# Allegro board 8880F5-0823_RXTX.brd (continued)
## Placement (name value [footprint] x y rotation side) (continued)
NOREF#2160  -  []  384.08 209.16 90 top
NOREF#2161  -  []  252.51 265.56 90 top
NOREF#2162  -  []  351.04 189.82 0 top
NOREF#2163  -  []  259.88 288.41 90 top
NOREF#2164  -  []  192.47 232.37 90 top
NOREF#2165  -  []  310.73 249.2 0 top
NOREF#2166  -  []  390.53 154.88 0 top
NOREF#2167  -  []  379.48 222.7 90 top
NOREF#2168  -  []  511.59 273.87 90 top
NOREF#2169  -  []  412.62 273.37 0 top
NOREF#2170  -  []  94.93 190.55 0 top
NOREF#2171  -  []  263.95 163.52 90 top
NOREF#2172  -  []  383.09 289.12 0 top
NOREF#2173  -  []  229.51 193.69 0 top
NOREF#2174  -  []  303.84 288.86 0 top
NOREF#2175  -  []  167.7 229.07 90 top
NOREF#2176  -  []  453.88 171.53 0 top
NOREF#2177  -  []  327.27 131.64 90 top
NOREF#2178  -  []  182.57 158.5 0 top
NOREF#2179  -  []  252.51 205.55 0 top
NOREF#2180  -  []  383.09 224.85 0 top
NOREF#2181  -  []  209.23 216.45 90 top
NOREF#2182  -  []  400.85 265.37 0 top
NOREF#2183  -  []  330.17 163.82 90 top
NOREF#2184  -  []  383.09 241.11 0 top
NOREF#2185  -  []  518.38 290.38 90 top
NOREF#2186  -  []  182.82 230.19 90 top
NOREF#2187  -  []  272.25 244.23 0 top
NOREF#2188  -  []  406.19 171.64 0 top
NOREF#2189  -  []  167.7 260.9 90 top
NOREF#2190  -  []  413.51 207.71 90 top
NOREF#2191  -  []  175.7 162.1 90 top
NOREF#2192  -  []  209.23 202.99 90 top
NOREF#2193  -  []  331.86 252.43 90 top
NOREF#2194  -  []  471.21 168.33 90 top
NOREF#2195  -  []  250.74 164.72 0 top
NOREF#2196  -  []  256.45 164.74 0 top
NOREF#2197  -  []  390.94 257.16 90 top
NOREF#2198  -  []  167.7 247.18 90 top
NOREF#2199  -  []  215.96 248.49 0 top
NOREF#2200  -  []  184.89 159.1 90 top
NOREF#2201  -  []  377.32 180.15 0 top
NOREF#2202  -  []  423.61 182.42 90 top
NOREF#2203  -  []  330.17 225.04 90 top
NOREF#2204  -  []  230.41 243.09 90 top
NOREF#2205  -  []  309.51 249.2 0 top
NOREF#2206  -  []  329.85 164.72 0 top
NOREF#2207  -  []  184.89 172.56 90 top
NOREF#2208  -  []  450.03 166.93 0 top
NOREF#2209  -  []  194.09 187.32 90 top
NOREF#2210  -  []  381.86 129.99 0 top
NOREF#2211  -  []  201.23 192.32 90 top
NOREF#2212  -  []  327.25 265.55 0 top
NOREF#2213  -  []  192.57 256.4 90 top
NOREF#2214  -  []  392.24 193.43 90 top
NOREF#2215  -  []  182.57 158.5 90 top
NOREF#2216  -  []  167.7 134.07 90 top
NOREF#2217  -  []  388.43 180.15 0 top
NOREF#2218  -  []  184.47 200.54 90 top
NOREF#2219  -  []  199.33 226.57 0 top
NOREF#2220  -  []  230.73 249.2 0 top
NOREF#2221  -  []  248.33 187.93 0 top
NOREF#2222  -  []  229.51 249.2 0 top
NOREF#2223  -  []  478.57 274.77 90 top
NOREF#2224  -  []  247.57 264.65 90 top
NOREF#2225  -  []  201.23 200.54 0 top
NOREF#2226  -  []  334.29 265.56 0 top
NOREF#2227  -  []  420.62 239.21 90 top
NOREF#2228  -  []  192.47 222.95 90 top
NOREF#2229  -  []  167.7 206.29 90 top
NOREF#2230  -  []  237.83 257.63 0 top
NOREF#2231  -  []  298.16 188.49 0 top
NOREF#2232  -  []  194.09 255.9 90 top
NOREF#2233  -  []  124.61 178.64 0 top
NOREF#2234  -  []  336.45 224.74 0 top
NOREF#2235  -  []  399.39 178.25 0 top
NOREF#2236  -  []  172.08 275.14 90 top
NOREF#2237  -  []  101.82 290.38 90 top
NOREF#2238  -  []  321.82 227.13 90 top
NOREF#2239  -  []  262.68 224.74 90 top
NOREF#2240  -  []  260.99 135.19 90 top
NOREF#2241  -  []  230.73 189.2 0 top
NOREF#2242  -  []  201.23 233.47 90 top
NOREF#2243  -  []  420.62 271.47 90 top
NOREF#2244  -  []  238.45 257.01 0 top
NOREF#2245  -  []  410.27 257.37 0 top
NOREF#2246  -  []  263.95 224.74 90 top
NOREF#2247  -  []  184.47 186.57 90 top
NOREF#2248  -  []  394.46 129.99 90 top
NOREF#2249  -  []  229.21 253.37 0 top
NOREF#2250  -  []  119.95 195.15 0 top
NOREF#2251  -  []  451.68 214.96 0 top
NOREF#2252  -  []  387.08 154.88 0 top
NOREF#2253  -  []  367.13 271.21 0 top
NOREF#2254  -  []  309.51 193.69 0 top
NOREF#2255  -  []  400.91 207.71 0 top
NOREF#2256  -  []  251.05 264.65 90 top
NOREF#2257  -  []  209.23 230.17 90 top
NOREF#2258  -  []  330.73 205.55 0 top
NOREF#2259  -  []  387.39 265.11 0 top
NOREF#2260  -  []  232.25 271.67 90 top
NOREF#2261  -  []  251.62 265.56 0 top
NOREF#2262  -  []  331.05 265.86 90 top
NOREF#2263  -  []  217.41 213.24 90 top
NOREF#2264  -  []  318.45 257.01 0 top
NOREF#2265  -  []  473.7 176.22 90 top
NOREF#2266  -  []  451.64 179.06 0 top
NOREF#2267  -  []  318.32 131.64 0 top
NOREF#2268  -  []  277.17 288.86 0 top
NOREF#2269  -  []  165.8 185.42 0 top
NOREF#2270  -  []  378.75 240.56 90 top
NOREF#2271  -  []  199.33 212.85 0 top
NOREF#2272  -  []  230.73 187.93 0 top
NOREF#2273  -  []  175.7 230.17 90 top
NOREF#2274  -  []  251.54 192.73 90 top
NOREF#2275  -  []  384.36 131.89 0 top
NOREF#2276  -  []  167.7 241.43 0 top
NOREF#2277  -  []  184.47 173.11 90 top
NOREF#2278  -  []  392.47 240.66 90 top
NOREF#2279  -  []  403.99 171.64 0 top
NOREF#2280  -  []  400.25 148.15 90 top
NOREF#2281  -  []  318.32 131.64 0 top
NOREF#2282  -  []  317.05 288.86 0 top
NOREF#2283  -  []  268.94 272.1 0 top
NOREF#2284  -  []  272.25 241.69 0 top
NOREF#2285  -  []  310.73 183.41 0 top
NOREF#2286  -  []  167.7 186.57 0 top
NOREF#2287  -  []  346.27 135.17 90 top
NOREF#2288  -  []  385.19 297.12 0 top
NOREF#2289  -  []  376.98 224.6 0 top
NOREF#2290  -  []  247.25 204.35 90 top
NOREF#2291  -  []  254.61 264.65 90 top
NOREF#2292  -  []  337.09 223.52 90 top
NOREF#2293  -  []  303.56 173.86 90 top
NOREF#2294  -  []  451.68 171.53 0 top
NOREF#2295  -  []  300.11 273.24 90 top
NOREF#2296  -  []  415.1 163.64 0 top
NOREF#2297  -  []  110.47 171.02 0 top
NOREF#2298  -  []  300.36 248.49 0 top
NOREF#2299  -  []  451.68 195.91 0 top
NOREF#2300  -  []  475.04 195.66 0 top
NOREF#2301  -  []  352.25 189.18 90 top
NOREF#2302  -  []  337.9 186.99 0 top
NOREF#2303  -  []  459.28 227 0 top
NOREF#2304  -  []  185.2 273.5 90 top
NOREF#2305  -  []  117.33 247.35 90 top
NOREF#2306  -  []  401.87 194.18 90 top
NOREF#2307  -  []  182.57 226.57 90 top
NOREF#2308  -  []  217.41 273.24 90 top
NOREF#2309  -  []  253.4 265.55 0 top
NOREF#2310  -  []  379 272.56 90 top
NOREF#2311  -  []  209.49 182.06 90 top
NOREF#2312  -  []  390.94 224.9 90 top
NOREF#2313  -  []  381.74 232.85 0 top
NOREF#2314  -  []  115.87 175.44 90 top
NOREF#2315  -  []  184.47 163.2 90 top
NOREF#2316  -  []  379.73 287.22 90 top
NOREF#2317  -  []  368.03 265.11 0 top
NOREF#2318  -  []  167.7 219.75 90 top
NOREF#2319  -  []  192.47 264.1 90 top
NOREF#2320  -  []  352.24 189.18 90 top
NOREF#2321  -  []  310.43 193.37 90 top
NOREF#2322  -  []  310.41 248.88 90 top
NOREF#2323  -  []  317.05 288.86 0 top
NOREF#2324  -  []  215.96 248.49 0 top
NOREF#2325  -  []  296.96 240.71 0 top
NOREF#2326  -  []  310.73 253.69 0 top
NOREF#2327  -  []  465.45 273.87 90 top
NOREF#2328  -  []  260.99 143.19 0 top
NOREF#2329  -  []  298.16 177.06 0 top
NOREF#2330  -  []  93.76 273.87 90 top
NOREF#2331  -  []  461.86 230.75 0 top
NOREF#2332  -  []  272.25 184.23 0 top
NOREF#2333  -  []  450.03 182.17 0 top
NOREF#2334  -  []  315.7 296.86 0 top
NOREF#2335  -  []  331.62 265.56 0 top
NOREF#2336  -  []  302.49 296.86 0 top
NOREF#2337  -  []  327.89 204.35 90 top
NOREF#2338  -  []  118.45 226.62 90 top
NOREF#2339  -  []  511.59 293.82 90 top
NOREF#2340  -  []  403.41 209.61 0 top
NOREF#2341  -  []  271.04 244.23 0 top
NOREF#2342  -  []  192.47 209.49 90 top
NOREF#2343  -  []  107.02 171.57 0 top
NOREF#2344  -  []  324.65 288.86 0 top
NOREF#2345  -  []  165.8 171.96 90 top
NOREF#2346  -  []  287.27 286.96 90 top
NOREF#2347  -  []  313.98 143.79 90 top
NOREF#2348  -  []  352.55 189.5 0 top
NOREF#2349  -  []  184.47 227.72 0 top
NOREF#2350  -  []  395.07 129.99 0 top
NOREF#2351  -  []  295.96 248.49 0 top
NOREF#2352  -  []  411.26 163.09 90 top
NOREF#2353  -  []  332.51 205.56 0 top
NOREF#2354  -  []  473.6 162.62 90 top
NOREF#2355  -  []  379.48 255.21 90 top
NOREF#2356  -  []  184.47 173.11 0 top
NOREF#2357  -  []  175.7 135.17 90 top
NOREF#2358  -  []  333.33 181.33 90 top
NOREF#2359  -  []  392.24 193.43 0 top
NOREF#2360  -  []  251.94 264.65 90 top
NOREF#2361  -  []  271.04 181.69 0 top
NOREF#2362  -  []  127.84 167.9 90 top
NOREF#2363  -  []  392.04 273.11 90 top
NOREF#2364  -  []  251.86 192.43 90 top
NOREF#2365  -  []  234.7 298.51 0 top
NOREF#2366  -  []  375.22 163.39 0 top
NOREF#2367  -  []  229.51 183.41 0 top
NOREF#2368  -  []  387.39 249.11 0 top
NOREF#2369  -  []  304.61 144.34 0 top
NOREF#2370  -  []  199.33 199.39 90 top
NOREF#2371  -  []  398.65 209.36 90 top
NOREF#2372  -  []  101.82 273.87 90 top
NOREF#2373  -  []  396.55 257.37 0 top
NOREF#2374  -  []  199.08 254 0 top
NOREF#2375  -  []  401.89 163.64 0 top
NOREF#2376  -  []  391.96 131.89 0 top
NOREF#2377  -  []  271.04 241.69 0 top
NOREF#2378  -  []  298.13 214.06 0 top
NOREF#2379  -  []  310.43 248.88 0 top
NOREF#2380  -  []  343.98 288.86 0 top
NOREF#2381  -  []  410.52 273.37 0 top
NOREF#2382  -  []  124.39 214.79 0 top
NOREF#2383  -  []  384.36 131.89 0 top
NOREF#2384  -  []  272.25 182.96 0 top
NOREF#2385  -  []  226.27 216.63 90 top
NOREF#2386  -  []  175.7 218.65 90 top
NOREF#2387  -  []  343.2 232.26 90 top
NOREF#2388  -  []  306.27 156.63 90 top
NOREF#2389  -  []  460.93 234.74 90 top
NOREF#2390  -  []  289.01 272.1 0 top
NOREF#2391  -  []  461.86 187.32 0 top
NOREF#2392  -  []  120.21 178.64 0 top
NOREF#2393  -  []  230.73 183.41 0 top
NOREF#2394  -  []  396.55 289.12 0 top
NOREF#2395  -  []  331.62 264.35 90 top
NOREF#2396  -  []  201.49 161 90 top
NOREF#2397  -  []  479.44 195.66 0 top
NOREF#2398  -  []  184.47 206.29 90 top
NOREF#2399  -  []  390.69 289.12 0 top
NOREF#2400  -  []  339.65 204.65 90 top
NOREF#2401  -  []  112.41 195.15 0 top
NOREF#2402  -  []  244.8 288.61 0 top
NOREF#2403  -  []  257.9 246.35 90 top
NOREF#2404  -  []  262.34 143.19 0 top
NOREF#2405  -  []  297.41 213.24 90 top
NOREF#2406  -  []  312.46 144.39 90 top
NOREF#2407  -  []  418.12 241.11 0 top
NOREF#2408  -  []  304.61 144.34 0 top
NOREF#2409  -  []  317.57 209.63 90 top
NOREF#2410  -  []  264.29 272.1 90 top
NOREF#2411  -  []  346.27 135.17 90 top
NOREF#2412  -  []  468.85 259.9 90 top
NOREF#2413  -  []  310.43 243.09 90 top
NOREF#2414  -  []  395.2 249.11 0 top
NOREF#2415  -  []  230.43 248.88 90 top
NOREF#2416  -  []  368.03 232.6 0 top
NOREF#2417  -  []  229.05 211.67 0 top
NOREF#2418  -  []  392.47 288.57 90 top
NOREF#2419  -  []  194.09 242.18 90 top
NOREF#2420  -  []  342.68 164.74 90 top
NOREF#2421  -  []  390.53 163.64 0 top
NOREF#2422  -  []  485.36 292.02 90 top
NOREF#2423  -  []  168.13 145.38 90 top
NOREF#2424  -  []  320.42 139.64 0 top
NOREF#2425  -  []  184.89 240.88 90 top
NOREF#2426  -  []  201.21 292.55 90 top
NOREF#2427  -  []  385.32 161.49 90 top
NOREF#2428  -  []  184.89 227.17 90 top
NOREF#2429  -  []  459.28 183.57 90 top
NOREF#2430  -  []  182.82 162.12 90 top
NOREF#2431  -  []  250.49 164.74 90 top
NOREF#2432  -  []  93.76 271.33 90 top
NOREF#2433  -  []  199.84 148.65 90 top
NOREF#2434  -  []  272.24 241.05 90 top
NOREF#2435  -  []  339.33 264.35 90 top
NOREF#2436  -  []  166.06 243.9 90 top
NOREF#2437  -  []  462.06 277.31 90 top
NOREF#2438  -  []  175.7 243.88 90 top
NOREF#2439  -  []  272.25 242.32 90 top
NOREF#2440  -  []  239.33 176.03 90 top
NOREF#2441  -  []  394.66 290.39 90 top
NOREF#2442  -  []  470.79 128.27 0 top
NOREF#2443  -  []  286.55 288.31 90 top
NOREF#2444  -  []  327.89 264.35 90 top
NOREF#2445  -  []  251.62 265.55 0 top
NOREF#2446  -  []  175.7 195.52 90 top
NOREF#2447  -  []  209.49 162.1 90 top
NOREF#2448  -  []  166.06 257.62 90 top
NOREF#2449  -  []  334.61 204.65 90 top
NOREF#2450  -  []  396.55 225.11 0 top
NOREF#2451  -  []  106.76 210.11 90 top
NOREF#2452  -  []  201.49 147.53 90 top
NOREF#2453  -  []  165.8 240.28 0 top
NOREF#2454  -  []  369.38 224.6 0 top
NOREF#2455  -  []  419.9 240.56 90 top
NOREF#2456  -  []  184.89 186.02 90 top
NOREF#2457  -  []  118.96 179.19 0 top
NOREF#2458  -  []  101.82 271.33 90 top
NOREF#2459  -  []  413.75 171.64 0 top
NOREF#2460  -  []  331.62 205.56 90 top
NOREF#2461  -  []  463.61 171.53 0 top
NOREF#2462  -  []  184.47 219.75 90 top
NOREF#2463  -  []  251.06 165.04 90 top
NOREF#2464  -  []  115.36 235.64 90 top
NOREF#2465  -  []  405.93 272.66 90 top
NOREF#2466  -  []  377.23 289.12 0 top
NOREF#2467  -  []  479.44 239.09 0 top
NOREF#2468  -  []  528.1 276.41 90 top
NOREF#2469  -  []  175.7 189.02 90 top
NOREF#2470  -  []  459.28 168.33 90 top
NOREF#2471  -  []  327.25 205.55 0 top
NOREF#2472  -  []  272.55 185.18 0 top
NOREF#2473  -  []  346.08 296.86 0 top
NOREF#2474  -  []  165.8 171.96 0 top
NOREF#2475  -  []  36.1 131.91 0 top
NOREF#2476  -  []  127.95 187.53 0 top
NOREF#2477  -  []  249.6 164.74 90 top
NOREF#2478  -  []  384.59 162.84 90 top
NOREF#2479  -  []  411.26 209.66 90 top
NOREF#2480  -  []  451.68 230.2 0 top
NOREF#2481  -  []  250.73 205.56 0 top
NOREF#2482  -  []  352.25 249.82 0 top
NOREF#2483  -  []  451.68 171.53 0 top
NOREF#2484  -  []  462.06 274.77 90 top
NOREF#2485  -  []  386.33 207.21 90 top
NOREF#2486  -  []  393.19 287.22 90 top
NOREF#2487  -  []  128.21 178.64 0 top
NOREF#2488  -  []  400.24 198.08 90 top
NOREF#2489  -  []  200.98 260.9 90 top
NOREF#2490  -  []  108.01 222.33 0 top
NOREF#2491  -  []  263.2 172.26 90 top
NOREF#2492  -  []  249.28 223.82 90 top
NOREF#2493  -  []  35.83 132.61 0 top
NOREF#2494  -  []  337.09 163.52 90 top
NOREF#2495  -  []  263.31 224.74 0 top
NOREF#2496  -  []  461.96 210.36 0 top
NOREF#2497  -  []  192.47 164.3 90 top
NOREF#2498  -  []  418.12 257.42 90 top
NOREF#2499  -  []  115.61 211.51 90 top
NOREF#2500  -  []  461.86 225.6 90 top
NOREF#2501  -  []  352.93 288.86 90 top
NOREF#2502  -  []  394.05 255.47 0 top
NOREF#2503  -  []  463.61 222.58 0 top
NOREF#2504  -  []  259.97 264.35 90 top
NOREF#2505  -  []  392.47 272.56 90 top
NOREF#2506  -  []  398.53 178.25 90 top
NOREF#2507  -  []  471.21 211.76 0 top
NOREF#2508  -  []  485.36 259.9 90 top
NOREF#2509  -  []  303.56 185.29 90 top
NOREF#2510  -  []  334.61 205.86 90 top
NOREF#2511  -  []  386.53 181.42 90 top
NOREF#2512  -  []  368.28 281.11 0 top
NOREF#2513  -  []  254.29 205.55 0 top
NOREF#2514  -  []  194.09 160.4 90 top
NOREF#2515  -  []  383.09 273.11 0 top
NOREF#2516  -  []  465.31 186.77 0 top
NOREF#2517  -  []  449.99 174.46 0 top
NOREF#2518  -  []  253.53 140.14 0 top
NOREF#2519  -  []  229.21 243.09 0 top
NOREF#2520  -  []  201.49 178.86 90 top
NOREF#2521  -  []  199.33 185.42 90 top
NOREF#2522  -  []  230.73 189.2 0 top
NOREF#2523  -  []  392.04 257.11 90 top
NOREF#2524  -  []  461.96 166.93 0 top
NOREF#2525  -  []  330.74 224.74 0 top
NOREF#2526  -  []  383.09 224.85 0 top
NOREF#2527  -  []  249.85 224.74 0 top
NOREF#2528  -  []  259.33 205.55 0 top
NOREF#2529  -  []  310.73 189.2 0 top
NOREF#2530  -  []  352.24 242.32 90 top
NOREF#2531  -  []  242.23 173.13 0 top
NOREF#2532  -  []  309.51 187.93 0 top
NOREF#2533  -  []  242.23 233.13 0 top
NOREF#2534  -  []  329.28 165.04 90 top
NOREF#2535  -  []  182.57 144.78 90 top
NOREF#2536  -  []  471.21 219.38 0 top
NOREF#2537  -  []  105.93 204.27 90 top
NOREF#2538  -  []  420.15 131.44 90 top
NOREF#2539  -  []  184.47 151.68 90 top
NOREF#2540  -  []  230.43 194.01 0 top
NOREF#2541  -  []  354.27 134.07 90 top
NOREF#2542  -  []  210.86 242.18 90 top
NOREF#2543  -  []  310.43 188.88 90 top
NOREF#2544  -  []  75.98 287.84 90 top
NOREF#2545  -  []  184.47 214 0 top
NOREF#2546  -  []  314.33 228.13 90 top
NOREF#2547  -  []  329.6 223.52 90 top
NOREF#2548  -  []  109.96 238.84 0 top
NOREF#2549  -  []  271.04 245.5 0 top
NOREF#2550  -  []  118.74 215.34 0 top
NOREF#2551  -  []  310.41 247.61 90 top
NOREF#2552  -  []  296.96 192.14 0 top
NOREF#2553  -  []  334.29 205.56 0 top
NOREF#2554  -  []  354.27 131.87 90 top
NOREF#2555  -  []  167.7 214 0 top
NOREF#2556  -  []  298.16 237.06 0 top
NOREF#2557  -  []  397.8 146.33 90 top
NOREF#2558  -  []  248 286.96 0 top
NOREF#2559  -  []  318.45 197.01 0 top
NOREF#2560  -  []  230.41 247.61 90 top
NOREF#2561  -  []  263.71 288.86 0 top
NOREF#2562  -  []  409.17 249.11 0 top
NOREF#2563  -  []  405.93 272.56 90 top
NOREF#2564  -  []  396.28 146.93 90 top
NOREF#2565  -  []  201.23 227.72 0 top
NOREF#2566  -  []  229.51 186.66 0 top
NOREF#2567  -  []  118.99 171.65 0 top
NOREF#2568  -  []  424.55 146.88 90 top
NOREF#2569  -  []  301.34 286.96 0 top
NOREF#2570  -  []  339.65 264.65 90 top
NOREF#2571  -  []  453.84 179.06 0 top
NOREF#2572  -  []  401.89 163.64 0 top
R1  NC/1M-1-S4  [R0402]  221.23 227.84 180 bottom
R2  NC/1M-1-S4  [R0402]  218.95 227.84 0 bottom
R3  NC/100K-1-S4  [R0402]  184.15 131.06 180 bottom
R4  NC/100K-1-S4  [R0402]  181.61 131.06 180 bottom
R5  0-5-S4  [R0402]  222.38 272.16 270 bottom
R6  1M-1-S4  [R0402]  222.38 274.32 270 bottom
R7  49.9-1-S4  [R0402]  178.5 217.52 90 bottom
R8  49.9-1-S4  [R0402]  178.5 215.38 90 bottom
R9  49.9-1-S4  [R0402]  164.91 217.52 90 bottom
R10  49.9-1-S4  [R0402]  164.91 215.38 90 bottom
R11  49.9-1-S4  [R0402]  212.03 231.24 90 bottom
R12  49.9-1-S4  [R0402]  212.03 229.1 90 bottom
R13  49.9-1-S4  [R0402]  198.44 231.24 90 bottom
R14  49.9-1-S4  [R0402]  198.44 229.1 90 bottom
R15  49.9-1-S4  [R0402]  296.06 299.66 180 bottom
R16  49.9-1-S4  [R0402]  298.21 299.66 180 bottom
R17  49.9-1-S4  [R0402]  296.06 286.07 180 bottom
R18  49.9-1-S4  [R0402]  298.21 286.07 180 bottom
R19  49.9-1-S4  [R0402]  309.27 299.66 180 bottom
R20  49.9-1-S4  [R0402]  311.42 299.66 180 bottom
R21  49.9-1-S4  [R0402]  309.27 286.07 180 bottom
R22  49.9-1-S4  [R0402]  311.42 286.07 180 bottom
R23  49.9-1-S4  [R0402]  349.4 299.66 180 bottom
R24  49.9-1-S4  [R0402]  351.55 299.66 180 bottom
R25  49.9-1-S4  [R0402]  349.4 286.07 180 bottom
R26  49.9-1-S4  [R0402]  351.55 286.07 180 bottom
R27  49.9-1-S4  [R0402]  335.94 299.66 180 bottom
R28  49.9-1-S4  [R0402]  338.09 299.66 180 bottom
R29  49.9-1-S4  [R0402]  335.94 286.07 180 bottom
R30  49.9-1-S4  [R0402]  338.09 286.07 180 bottom
R31  49.9-1-S4  [R0402]  322.48 299.66 180 bottom
R32  49.9-1-S4  [R0402]  324.62 299.66 180 bottom
R33  49.9-1-S4  [R0402]  322.48 286.07 180 bottom
R34  49.9-1-S4  [R0402]  324.62 286.07 180 bottom
R37  49.9-1-S4  [R0402]  269.14 286.07 180 bottom
R38  49.9-1-S4  [R0402]  271.28 286.07 180 bottom
R39  49.9-1-S4  [R0402]  287.88 269.3 0 bottom
R40  49.9-1-S4  [R0402]  285.74 269.3 0 bottom
R41  49.9-1-S4  [R0402]  287.88 282.89 0 bottom
R42  49.9-1-S4  [R0402]  285.74 282.89 0 bottom
R43  49.9-1-S4  [R0402]  164.91 258.67 90 bottom
R44  49.9-1-S4  [R0402]  164.91 256.53 90 bottom
R45  49.9-1-S4  [R0402]  198.44 244.96 90 bottom
R46  49.9-1-S4  [R0402]  198.44 242.81 90 bottom
R47  49.9-1-S4  [R0402]  195.26 231.24 90 bottom
R48  49.9-1-S4  [R0402]  195.26 229.1 90 bottom
R49  49.9-1-S4  [R0402]  181.67 231.24 90 bottom
R50  49.9-1-S4  [R0402]  181.67 229.1 90 bottom
R51  49.9-1-S4  [R0402]  178.5 231.24 90 bottom
R52  49.9-1-S4  [R0402]  178.5 229.1 90 bottom
R53  49.9-1-S4  [R0402]  164.91 231.24 90 bottom
R54  49.9-1-S4  [R0402]  164.91 229.1 90 bottom
R55  49.9-1-S4  [R0402]  211.77 258.67 90 bottom
R56  49.9-1-S4  [R0402]  211.77 256.53 90 bottom
R57  49.9-1-S4  [R0402]  198.18 258.67 90 bottom
R58  49.9-1-S4  [R0402]  198.18 256.53 90 bottom
R59  49.9-1-S4  [R0402]  195.26 244.96 90 bottom
R60  49.9-1-S4  [R0402]  195.26 242.81 90 bottom
R61  49.9-1-S4  [R0402]  181.67 244.96 90 bottom
R62  49.9-1-S4  [R0402]  181.67 242.81 90 bottom
R63  49.9-1-S4  [R0402]  195.26 258.67 90 bottom
R64  49.9-1-S4  [R0402]  195.26 256.53 90 bottom
R65  49.9-1-S4  [R0402]  164.91 244.96 90 bottom
R66  49.9-1-S4  [R0402]  164.91 242.81 90 bottom
R67  49.9-1-S4  [R0402]  239.37 285.81 0 bottom
R68  49.9-1-S4  [R0402]  237.22 285.81 0 bottom
R69  49.9-1-S4  [R0402]  239.37 299.4 0 bottom
R70  49.9-1-S4  [R0402]  237.22 299.4 0 bottom
R71  49.9-1-S4  [R0402]  255.93 299.66 180 bottom
R72  49.9-1-S4  [R0402]  258.08 299.66 180 bottom
R73  49.9-1-S4  [R0402]  255.93 286.07 180 bottom
R74  49.9-1-S4  [R0402]  258.08 286.07 180 bottom
R75  49.9-1-S4  [R0402]  282.6 299.66 180 bottom
R76  49.9-1-S4  [R0402]  284.75 299.66 180 bottom
R77  49.9-1-S4  [R0402]  282.6 286.07 180 bottom
R78  49.9-1-S4  [R0402]  284.75 286.07 180 bottom
R79  49.9-1-S4  [R0402]  178.5 258.67 90 bottom
R80  49.9-1-S4  [R0402]  178.5 256.53 90 bottom
R82  4.7K-1-S4-WA  [R0402]  122.62 241.1 180 bottom
R83  4.7K-1-S4-WA  [R0402]  96.77 233.43 180 bottom
R84  4.7K-1-S4-WA  [R0402]  96.77 241.05 180 bottom
R85  100K-1-S4  [R0402]  113.79 230.12 180 bottom
R86  4.7K-1-S4-WA  [R0402]  93.33 207.46 180 bottom
R87  4.7K-1-S4-WA  [R0402]  104.14 203.31 180 bottom
R88  4.7K-1-S4-WA  [R0402]  101.6 203.31 180 bottom
R89  4.7K-1-S4-WA  [R0402]  89.03 207.41 0 bottom
R90  4.7K-1-S4-WA  [R0402]  101.6 215.5 180 bottom
R91  4.7K-1-S4-WA  [R0402]  99.06 215.5 180 bottom
R92  4.7K-1-S4-WA  [R0402]  96.52 215.5 180 bottom
R93  4.7K-1-S4-WA  [R0402]  93.33 221.18 180 bottom
R94  4.7K-1-S4-WA  [R0402]  104.25 216.86 0 bottom
R95  4.7K-1-S4-WA  [R0402]  101.7 216.91 180 bottom
R96  4.7K-1-S4-WA  [R0402]  89.27 221.18 0 bottom
R97  4.7K-1-S4-WA  [R0402]  101.7 229.1 180 bottom
R98  4.7K-1-S4-WA  [R0402]  99.16 229.1 180 bottom
R99  4.7K-1-S4-WA  [R0402]  96.62 229.1 180 bottom
R100  49.9-1-S4  [R0402]  181.67 258.67 90 bottom
R101  49.9-1-S4  [R0402]  181.67 256.53 90 bottom
R102  49.9-1-S4  [R0402]  212.03 244.96 90 bottom
R103  49.9-1-S4  [R0402]  212.03 242.81 90 bottom
R104  49.9-1-S4  [R0402]  178.5 244.96 90 bottom
R105  49.9-1-S4  [R0402]  178.5 242.81 90 bottom
R117  1K-1-S4  [R0402]  127.2 241.1 180 bottom
R118  NC/0-5-S4  [R0402]  230.41 245.39 180 bottom
R119  4.7K-1-S4-WA  [R0402]  127.25 233.43 0 bottom
R120  4.7K-1-S4-WA  [R0402]  127.25 225.81 0 bottom
R125  0-5-S4  [R0402]  123.19 224.54 180 bottom
R126  0-5-S4  [R0402]  127.25 224.54 180 bottom
R127  0-5-S4  [R0402]  122.94 216.92 180 bottom
R128  0-5-S4  [R0402]  127.51 216.92 180 bottom
R129  0-5-S4  [R0402]  221.23 229.11 180 bottom
R130  0-5-S4  [R0402]  218.95 229.11 0 bottom
R131  50-0.1-S4-HF-VI  [R0402]  223.77 243.33 90 bottom
R132  50-0.1-S4-HF-VI  [R0402]  216.15 243.33 90 bottom
R133  0-5-S4  [R0402]  222.38 276.48 90 bottom
RB1  10K-1-S6  [R0603]  212.47 13.59 0 bottom
RB2  10K-1-S6  [R0603]  212.47 12.06 0 bottom
S1_I2C  HDR-4X1-MR-A  [JP_4P_100_R90_V1]  62.99 209.04 270 top
S1_RST_N  HDR-2X1-M  [JP_2P_100]  115.82 232.41 270 bottom
S2_I2C  HDR-4X1-MR-A  [JP_4P_100_R90_V1]  497.33 203.45 270 top
S2_RST_N  HDR-2X1-M  [JP_2P_100]  463.04 233.43 90 bottom
S3_I2C  HDR-4X1-MR-A  [JP_4P_100_R90_V1]  75.69 209.04 270 top
S3_RST_N  HDR-2X1-M  [JP_2P_100]  116.08 188.72 270 bottom
S4_I2C  HDR-4X1-MR-A  [JP_4P_100_R90_V1]  511.3 203.45 270 top
S4_RST_N  HDR-2X1-M  [JP_2P_100]  463.04 189.99 90 bottom
SB1  SHORT  [DEFAULT_SHORT_SMALL]  402.59 11.04 90 top
SB2  SHORT  [DEFAULT_SHORT_SMALL]  328.93 417.83 270 top
SB3  SHORT  [DEFAULT_SHORT_SMALL]  255.27 11.71 90 top
SB8  SHORT  [DEFAULT_SHORT_SMALL]  179.07 418.32 270 top
SCREW1  V93KMFHOLE  [PG_VG93K_F_FULLOUTLINE]  290.83 214.63 0 top
SH1  SHORT  [DEFAULT_SHORT_SMALL]  185.19 290.72 0 top
SH2  SHORT  [DEFAULT_SHORT_SMALL]  187.14 290.72 0 top
SH3  SHORT  [DEFAULT_SHORT_SMALL]  175.35 290.72 0 top
SH4  SHORT  [DEFAULT_SHORT_SMALL]  173.4 290.85 180 top
SH5  SHORT  [DEFAULT_SHORT_SMALL]  118.2 289.45 0 top
SH6  SHORT  [DEFAULT_SHORT_SMALL]  116.25 289.58 180 top
SH7  SHORT  [DEFAULT_SHORT_SMALL]  168.68 290.72 0 top
SH8  SHORT  [DEFAULT_SHORT_SMALL]  156.89 290.85 180 top
SH9  SHORT  [DEFAULT_SHORT_SMALL]  170.63 290.72 0 top
SH10  SHORT  [DEFAULT_SHORT_SMALL]  158.84 290.72 0 top
SH11  SHORT  [DEFAULT_SHORT_SMALL]  173.4 274.34 180 top
SH12  SHORT  [DEFAULT_SHORT_SMALL]  185.19 274.21 0 top
SH13  SHORT  [DEFAULT_SHORT_SMALL]  203.14 290.72 0 top
SH14  SHORT  [DEFAULT_SHORT_SMALL]  201.19 290.72 0 top
SH15  SHORT  [DEFAULT_SHORT_SMALL]  189.4 290.85 180 top
SH16  SHORT  [DEFAULT_SHORT_SMALL]  191.35 290.72 0 top
SH17  SHORT  [DEFAULT_SHORT_SMALL]  156.89 274.34 180 top
SH18  SHORT  [DEFAULT_SHORT_SMALL]  168.68 274.21 0 top
SH19  SHORT  [DEFAULT_SHORT_SMALL]  99.42 246.45 0 top
SH20  SHORT  [DEFAULT_SHORT_SMALL]  101.62 246.45 0 top
SH21  SHORT  [DEFAULT_SHORT_SMALL]  94.56 246.5 0 top
SH22  SHORT  [DEFAULT_SHORT_SMALL]  96.76 246.5 0 top
SH23  SHORT  [DEFAULT_SHORT_SMALL]  201.19 274.21 0 top
SH24  SHORT  [DEFAULT_SHORT_SMALL]  203.37 274.08 180 top
SH25  SHORT  [DEFAULT_SHORT_SMALL]  175.35 274.21 0 top
SH26  SHORT  [DEFAULT_SHORT_SMALL]  187.14 274.21 0 top
SH27  SHORT  [DEFAULT_SHORT_SMALL]  158.84 274.21 0 top
SH28  SHORT  [DEFAULT_SHORT_SMALL]  170.63 274.21 0 top
SITE1  CU/HX8880-F05-LQFP176-20X20  [SK_LQFP176P_0P4MM_JG_HX8880]  250.83 244.63 90 top
SITE2  CU/HX8880-F05-LQFP176-20X20  [SK_LQFP176P_0P4MM_JG_HX8880]  330.83 244.63 90 top
SITE3  CU/HX8880-F05-LQFP176-20X20  [SK_LQFP176P_0P4MM_JG_HX8880]  250.83 184.63 90 top
SITE4  CU/HX8880-F05-LQFP176-20X20  [SK_LQFP176P_0P4MM_JG_HX8880]  330.83 184.63 90 top
SKB  Socket_Base_M5_140x140  [SOCKET_BASE_140X140_565100]  290.83 214.63 0 top
TP_AUXVCC  TP01  [TP_040_T]  101.29 247.61 180 top
TP_AVDD11_RX  TP01  [TP_040_T]  158.96 292.1 180 top
TP_AVDD11_XTAL  TP01  [TP_040_T]  201.21 275.59 0 top
TP_AVDD18_RX  TP01  [TP_040_T]  168.7 292.1 0 top
TP_PLL_M_VDD33  TP01  [TP_040_T]  201.21 292.1 0 top
TP_PLL_TX_VDD33  TP01  [TP_040_T]  191.48 292.1 180 top
TP_VCC3V3  TP01  [TP_040_T]  96.42 247.66 180 top
TP_VDD_IO_33  TP01  [TP_040_T]  175.47 292.1 180 top
TP_VDD_TXREG_33_B  TP01  [TP_040_T]  168.7 275.59 0 top
TP_VDD_TXREG_33_T  TP01  [TP_040_T]  158.96 275.59 180 top
TP_VDDA_33_LV  TP01  [TP_040_T]  185.21 292.1 0 top
TP_VDDC_11  TP01  [TP_040_T]  118.32 290.83 180 top
TP_VDDTXPST_11_B  TP01  [TP_040_T]  185.21 275.59 0 top
TP_VDDTXPST_11_T  TP01  [TP_040_T]  175.47 275.59 180 top
TP_XTAL_IN  TP01  [TP_040_T]  226.85 271.67 0 top
TP_XTAL_OUT  TP01  [TP_040_T]  226.85 276.97 0 top
TPL1  TPL01  [TPL_040_014_TB]  73.41 239.01 0 top
TPL2  TPL01  [TPL_040_014_TB]  78.49 244.09 0 top
TPL3  TPL01  [TPL_040_014_TB]  68.33 228.85 0 top
TPL4  TPL01  [TPL_040_014_TB]  68.33 239.01 0 top
TPL5  TPL01  [TPL_040_014_TB]  73.41 244.09 0 top
TPL6  TPL01  [TPL_040_014_TB]  68.33 233.93 0 top
TPL7  TPL01  [TPL_040_014_TB]  78.49 233.93 0 top
TPL8  TPL01  [TPL_040_014_TB]  73.41 233.93 0 top
TPL9  TPL01  [TPL_040_014_TB]  68.33 244.09 0 top
TPL10  TPL01  [TPL_040_014_TB]  78.49 239.01 0 top
TPL11  TPL01  [TPL_040_014_TB]  73.41 218.69 0 top
TPL12  TPL01  [TPL_040_014_TB]  78.49 218.69 0 top
TPL13  TPL01  [TPL_040_014_TB]  83.57 223.77 0 top
TPL14  TPL01  [TPL_040_014_TB]  83.57 218.69 0 top
TPL15  TPL01  [TPL_040_014_TB]  73.41 228.85 0 top
TPL16  TPL01  [TPL_040_014_TB]  68.33 223.77 0 top
TPL17  TPL01  [TPL_040_014_TB]  68.33 218.69 0 top
TPL18  TPL01  [TPL_040_014_TB]  78.49 223.77 0 top
TPL19  TPL01  [TPL_040_014_TB]  73.41 223.77 0 top
TPL20  TPL01  [TPL_040_014_TB]  78.49 228.85 0 top
TPL21  TPL01  [TPL_040_014_TB]  452.63 249.17 0 top
TPL22  TPL01  [TPL_040_014_TB]  452.63 259.33 0 top
TPL23  TPL01  [TPL_040_014_TB]  452.63 264.41 0 top
TPL24  TPL01  [TPL_040_014_TB]  452.63 254.25 0 top
TPL25  TPL01  [TPL_040_014_TB]  452.63 244.09 0 top
TPL26  TPL01  [TPL_040_014_TB]  457.71 244.09 0 top
TPL27  TPL01  [TPL_040_014_TB]  452.63 269.49 0 top
TPL28  TPL01  [TPL_040_014_TB]  457.71 249.17 0 top
TPL29  TPL01  [TPL_040_014_TB]  457.71 269.49 0 top
TPL30  TPL01  [TPL_040_014_TB]  457.71 264.41 0 top
TPL31  TPL01  [TPL_040_014_TB]  457.71 259.33 0 top
TPL32  TPL01  [TPL_040_014_TB]  457.71 254.25 0 top
TPL33  TPL01  [TPL_040_014_TB]  462.79 244.09 0 top
TPL34  TPL01  [TPL_040_014_TB]  467.87 249.17 0 top
TPL35  TPL01  [TPL_040_014_TB]  467.87 244.09 0 top
TPL36  TPL01  [TPL_040_014_TB]  462.79 249.17 0 top
TPL37  TPL01  [TPL_040_014_TB]  462.79 269.49 0 top
TPL38  TPL01  [TPL_040_014_TB]  462.79 259.33 0 top
TPL39  TPL01  [TPL_040_014_TB]  462.79 254.25 0 top
TPL40  TPL01  [TPL_040_014_TB]  462.79 264.41 0 top
U1  SOLDER-DIP8-SOCKET  [DIP8_300X100_RLPIN]  104.66 205.54 90 bottom
U2  SOLDER-DIP8-SOCKET  [DIP8_300X100_RLPIN]  104.76 219.15 90 bottom
UB1  AT24C04C-SSHM-SO8  [SO8_215X127MM]  218.44 13.97 180 bottom
UF1  MX25L4006EM2I-12G-SOP8  [SOCKET_CODE]  104.66 205.54 270 top
UF2  MX25L4006EM2I-12G-SOP8  [SOCKET_CODE]  104.75 219.2 270 top
UNK2C3  0.1U-16-X-S4-MU  [C0402]  289.81 132.08 180 bottom
UNK2C4  0.1U-16-X-S4-MU  [C0402]  287.27 132.08 180 bottom
UNK2C5  22P-50-N-S4-AVX  [C0402]  301.21 277.48 90 bottom
UNK2C6  22P-50-N-S4-AVX  [C0402]  301.21 271.16 270 bottom
UNK2C7  0.1U-16-X-S4-MU  [C0402]  468.12 235.71 180 bottom
UNK2C8  0.1U-16-X-S4-MU  [C0402]  475.39 204.98 0 bottom
UNK2C9  0.1U-16-X-S4-MU  [C0402]  475.49 218.59 0 bottom
UNK2CA1  NC/10U-10-X6S-S6-MU  [C0603]  462.91 293.37 0 bottom
UNK2CA2  NC/47U-10-X5R-S8-TDK  [C0805]  463.02 295.27 0 bottom
UNK2CA3  NC/10U-10-X6S-S6-MU  [C0603]  451.49 293.37 180 bottom
UNK2CA4  NC/47U-10-X5R-S8-TDK  [C0805]  451.38 295.27 180 bottom
UNK2CA5  NC/10U-10-X6S-S6-MU  [C0603]  484.5 293.37 180 bottom
UNK2CA6  NC/47U-10-X5R-S8-TDK  [C0805]  484.4 295.27 180 bottom
UNK2CA7  NC/10U-10-X6S-S6-MU  [C0603]  462.91 276.86 0 bottom
UNK2CA8  NC/47U-10-X5R-S8-TDK  [C0805]  463.02 278.76 0 bottom
UNK2CA9  NC/10U-10-X6S-S6-MU  [C0603]  451.49 276.86 180 bottom
UNK2CA10  NC/47U-10-X5R-S8-TDK  [C0805]  451.38 278.76 180 bottom
UNK2CA11  NC/10U-10-X6S-S6-MU  [C0603]  495.93 276.86 0 bottom
UNK2CA12  NC/47U-10-X5R-S8-TDK  [C0805]  496.04 278.76 0 bottom
UNK2CA13  NC/47U-10-X5R-S8-TDK  [C0805]  479.53 295.27 0 bottom
UNK2CA14  NC/10U-10-X6S-S6-MU  [C0603]  479.42 293.37 0 bottom
UNK2CA15  NC/47U-10-X5R-S8-TDK  [C0805]  467.89 295.27 180 bottom
UNK2CA16  NC/10U-10-X6S-S6-MU  [C0603]  468 293.37 180 bottom
UNK2CA17  NC/47U-10-X5R-S8-TDK  [C0805]  479.53 278.76 0 bottom
UNK2CA18  NC/10U-10-X6S-S6-MU  [C0603]  479.42 276.86 0 bottom
UNK2CA19  NC/47U-10-X5R-S8-TDK  [C0805]  91.09 249.81 180 bottom
UNK2CA20  NC/10U-10-X6S-S6-MU  [C0603]  91.19 247.9 180 bottom
UNK2CA21  10U-10-X6S-S6-MU  [C0603]  462.91 290.83 0 bottom
UNK2CA22  10U-10-X6S-S6-MU  [C0603]  451.49 290.83 180 bottom
UNK2CA23  10U-10-X6S-S6-MU  [C0603]  484.5 290.83 180 bottom
UNK2CA24  10U-10-X6S-S6-MU  [C0603]  462.91 274.32 0 bottom
UNK2CA25  10U-10-X6S-S6-MU  [C0603]  451.49 274.32 180 bottom
UNK2CA26  10U-10-X6S-S6-MU  [C0603]  495.93 274.32 0 bottom
UNK2CA27  10U-10-X6S-S6-MU  [C0603]  479.42 290.83 0 bottom
UNK2CA28  10U-10-X6S-S6-MU  [C0603]  468 290.83 180 bottom
UNK2CA29  10U-10-X6S-S6-MU  [C0603]  479.42 274.32 0 bottom
UNK2CA30  NC/47U-10-X5R-S8-TDK  [C0805]  86.22 249.86 180 bottom
UNK2CA31  10U-10-X6S-S6-MU  [C0603]  86.32 247.96 180 bottom
UNK2CA32  NC/10U-10-X6S-S6-MU  [C0603]  512.44 293.37 0 bottom
UNK2CA33  NC/47U-10-X5R-S8-TDK  [C0805]  512.55 295.27 0 bottom
UNK2CA34  10U-10-X6S-S6-MU  [C0603]  512.44 290.83 0 bottom
UNK2CA35  NC/10U-10-X6S-S6-MU  [C0603]  484.5 276.86 180 bottom
UNK2CA36  NC/47U-10-X5R-S8-TDK  [C0805]  484.4 278.76 180 bottom
UNK2CA37  10U-10-X6S-S6-MU  [C0603]  484.5 274.32 180 bottom
UNK2CA38  NC/10U-10-X6S-S6-MU  [C0603]  468 276.86 180 bottom
UNK2CA39  NC/47U-10-X5R-S8-TDK  [C0805]  467.89 278.76 180 bottom
UNK2CA40  10U-10-X6S-S6-MU  [C0603]  468 274.32 180 bottom
UNK2CC1  0.47U-10-X6S-S2-TY  [C0201]  317.98 224.12 90 bottom
UNK2CC2  4.7U-10-X6T-S4-MU  [C0402]  316.32 222.4 270 bottom
UNK2CC4  0.47U-10-X6S-S2-TY  [C0201]  309.81 247.93 0 bottom
UNK2CC6  0.47U-10-X6S-S2-TY  [C0201]  330.17 224.12 90 bottom
UNK2CC7  0.47U-10-X6S-S2-TY  [C0201]  309.81 246.66 0 bottom
UNK2CC8  0.47U-10-X6S-S2-TY  [C0201]  343.63 224.12 90 bottom
UNK2CC9  0.47U-10-X6S-S2-TY  [C0201]  334.61 266.16 270 bottom
UNK2CC11  0.47U-10-X6S-S2-TY  [C0201]  331.06 224.12 90 bottom
UNK2CC13  0.47U-10-X6S-S2-TY  [C0201]  336.77 224.12 90 bottom
UNK2CC15  4.7U-2.5-X6S-S2-MU  [C0201]  339.65 264.95 90 bottom
UNK2CC16  NC/4.7U-2.5-X6S-S2-MU  [C0201]  351.64 249.5 0 bottom
UNK2CC17  4.7U-2.5-X6S-S2-MU  [C0201]  309.81 253.69 0 bottom
UNK2CC19  0.47U-10-X6S-S2-TY  [C0201]  332.83 266.16 270 bottom
UNK2CC20  4.7U-10-X6T-S4-MU  [C0402]  334.11 267.66 0 bottom
UNK2CC22  0.47U-10-X6S-S2-TY  [C0201]  331.05 266.16 270 bottom
UNK2CC23  4.7U-10-X6T-S4-MU  [C0402]  330.34 253.09 270 bottom
UNK2CC25  0.47U-10-X6S-S2-TY  [C0201]  352.85 245.18 180 bottom
UNK2CC26  0.47U-10-X6S-S2-TY  [C0201]  333.72 266.16 270 bottom
UNK2CC27  0.47U-10-X6S-S2-TY  [C0201]  352.85 249.5 180 bottom
UNK2CC28  0.47U-10-X6S-S2-TY  [C0201]  339.65 266.16 270 bottom
UNK2CC29  0.47U-10-X6S-S2-TY  [C0201]  311.03 253.69 180 bottom
UNK2CC30  0.47U-10-X6S-S2-TY  [C0201]  309.81 243.41 0 bottom
UNK2CC31  0.47U-10-X6S-S2-TY  [C0201]  329.28 224.12 90 bottom
UNK2CC32  0.47U-10-X6S-S2-TY  [C0201]  342.36 224.12 90 bottom
UNK2CC33  0.47U-10-X6S-S2-TY  [C0201]  352.85 243.91 180 bottom
UNK2CC34  0.47U-10-X6S-S2-TY  [C0201]  331.94 266.16 270 bottom
UNK2CC35  0.47U-10-X6S-S2-TY  [C0201]  352.85 241.37 180 bottom
UNK2CC36  0.47U-10-X6S-S2-TY  [C0201]  352.85 242.64 180 bottom
UNK2CC37  0.47U-10-X6S-S2-TY  [C0201]  327.57 264.95 90 bottom
UNK2CC38  NC/4.7U-2.5-X6S-S2-MU  [C0201]  327.57 266.16 270 bottom
UNK2CC39  0.47U-10-X6S-S2-TY  [C0201]  311.03 249.2 180 bottom
UNK2CC40  4.7U-2.5-X6S-S2-MU  [C0201]  338.5 246.67 180 bottom
UNK2CC41  4.7U-2.5-X6S-S2-MU  [C0201]  309.81 249.2 0 bottom
UNK2CC42  4.7U-2.5-X6S-S2-MU  [C0201]  331.54 253.03 90 bottom
UNK2CD1  0.1U-10-X7R-S2-MU  [C0201]  317.98 225.34 270 top
UNK2CD3  0.1U-10-X7R-S2-MU  [C0201]  351.64 241.37 0 top
UNK2CD4  0.1U-10-X7R-S2-MU  [C0201]  334.61 264.95 90 top
UNK2CD5  0.1U-10-X7R-S2-MU  [C0201]  343.63 225.34 270 top
UNK2CD6  0.1U-10-X7R-S2-MU  [C0201]  311.03 246.66 180 top
UNK2CD7  0.1U-10-X7R-S2-MU  [C0201]  351.64 242.64 0 top
UNK2CD8  0.1U-10-X7R-S2-MU  [C0201]  331.06 225.34 270 top
UNK2CD9  0.1U-10-X7R-S2-MU  [C0201]  336.77 225.34 270 top
UNK2CD10  0.1U-10-X7R-S2-MU  [C0201]  351.64 249.5 0 top
UNK2CD11  0.1U-10-X7R-S2-MU  [C0201]  339.65 264.95 90 top
UNK2CD12  0.1U-10-X7R-S2-MU  [C0201]  311.03 253.69 180 top
UNK2CD13  0.1U-10-X7R-S2-MU  [C0201]  332.83 264.95 90 top
UNK2CD14  0.1U-10-X7R-S2-MU  [C0201]  331.05 264.95 90 top
UNK2CD15  0.1U-10-X7R-S2-MU  [C0201]  351.64 245.18 0 top
UNK2CD16  0.1U-10-X7R-S2-MU  [C0201]  333.72 264.95 90 top
UNK2CD17  0.1U-10-X7R-S2-MU  [C0201]  311.03 247.93 180 top
UNK2CD18  0.1U-10-X7R-S2-MU  [C0201]  331.94 264.95 90 top
UNK2CD19  0.1U-10-X7R-S2-MU  [C0201]  311.03 243.41 180 top
UNK2CD20  0.1U-10-X7R-S2-MU  [C0201]  351.64 243.91 0 top
UNK2CD21  0.1U-10-X7R-S2-MU  [C0201]  342.36 225.34 270 top
UNK2CD22  0.1U-10-X7R-S2-MU  [C0201]  329.28 225.34 270 top
UNK2CD23  0.1U-10-X7R-S2-MU  [C0201]  330.17 225.34 270 top
UNK2CD24  0.1U-10-X7R-S2-MU  [C0201]  327.57 264.95 90 top
UNK2CD25  0.1U-10-X7R-S2-MU  [C0201]  311.03 249.2 180 top
UNK2GND1  TP01  [TP_040_T]  450.43 295.27 0 top
UNK2GND2  TP01  [TP_040_T]  463.97 295.27 180 top
UNK2GND3  TP01  [TP_040_T]  483.45 295.27 0 top
UNK2GND4  TP01  [TP_040_T]  450.43 278.76 0 top
UNK2GND5  TP01  [TP_040_T]  463.97 278.76 180 top
UNK2GND6  TP01  [TP_040_T]  483.45 278.76 0 top
UNK2GND7  TP01  [TP_040_T]  480.48 295.27 180 top
UNK2GND8  TP01  [TP_040_T]  466.94 295.27 0 top
UNK2GND9  TP01  [TP_040_T]  480.48 278.76 180 top
UNK2GND10  TP01  [TP_040_T]  90.11 249.76 0 top
UNK2GND11  TP01  [TP_040_T]  85.24 249.81 0 top
UNK2GND12  TP01  [TP_040_T]  513.5 295.27 180 top
UNK2GND13  TP01  [TP_040_T]  496.99 278.76 180 top
UNK2GND14  TP01  [TP_040_T]  466.94 278.76 0 top
UNK2J1  HDR-2X1-M  [JP_2P_100]  468.63 233.43 90 bottom
UNK2J2  HDR-3X1-M  [JP_3P_100]  490.87 228.66 270 bottom
UNK2J3  HDR-3X1-M  [JP_3P_100]  490.87 214.94 270 bottom
UNK2J4  HDR-2X1-M  [JP_2P_100]  483.11 243.33 270 bottom
UNK2J5  HDR-2X1-M  [JP_2P_100]  483.11 231.65 270 bottom
UNK2K1  G6K-2F-RF-T-5V-SPECIAL  [RL_G6K2FRT_8P_5V_GR]  414.27 293.12 0 bottom
UNK2K2  G6K-2F-RF-T-5V-SPECIAL  [RL_G6K2FRT_8P_5V_GR]  414.27 277.37 0 bottom
UNK2K3  G6K-2F-RF-T-5V-SPECIAL  [RL_G6K2FRT_8P_5V_GR]  400.3 245.11 0 bottom
UNK2K4  G6K-2F-RF-T-5V-SPECIAL  [RL_G6K2FRT_8P_5V_GR]  373.38 277.11 0 bottom
UNK2K5  G6K-2F-RF-T-5V-SPECIAL  [RL_G6K2FRT_8P_5V_GR]  400.3 261.37 0 bottom
UNK2K6  G6K-2F-RF-T-5V-SPECIAL  [RL_G6K2FRT_8P_5V_GR]  400.3 277.11 0 bottom
UNK2K7  G6K-2F-RF-T-5V-SPECIAL  [RL_G6K2FRT_8P_5V_GR]  386.84 277.11 0 bottom
UNK2K8  G6K-2F-RF-T-5V-SPECIAL  [RL_G6K2FRT_8P_5V_GR]  386.84 293.12 0 bottom
UNK2K9  UA2-5NJ-A-V3  [RL_NECUA2_5V_V3]  299.96 235.46 90 bottom
UNK2K10  UA2-5NJ-A-V3  [RL_NECUA2_5V_V3]  467.11 228.6 180 bottom
UNK2K11  G6K-2F-RF-T-5V-SPECIAL  [RL_G6K2FRT_8P_5V_GR]  414.02 261.37 0 bottom
UNK2K12  UA2-5NJ-A-V3  [RL_NECUA2_5V_V3]  299.96 246.89 90 bottom
UNK2K13  UA2-5NJ-A-V3  [RL_NECUA2_5V_V3]  455.68 228.6 0 bottom
UNK2K14  UA2-5NJ-A-V3  [RL_NECUA2_5V_V3]  467.61 213.36 0 bottom
UNK2K15  UA2-5NJ-A-V3  [RL_NECUA2_5V_V3]  455.64 220.9 0 bottom
UNK2K16  G6K-2F-RF-T-5V-SPECIAL  [RL_G6K2FRT_8P_5V_GR]  373.13 261.11 0 bottom
UNK2K17  G6K-2F-RF-T-5V-SPECIAL  [RL_G6K2FRT_8P_5V_GR]  373.38 293.12 0 bottom
UNK2K18  UB2-5NU-B  [RL_NECUB2_5V]  308.45 274.32 0 bottom
UNK2K19  UA2-5NJ-A-V3  [RL_NECUA2_5V_V3]  467.61 220.98 0 bottom
UNK2K20  UA2-5NJ-A-V3  [RL_NECUA2_5V_V3]  455.68 213.36 0 bottom
UNK2K21  G6K-2F-RF-T-5V-SPECIAL  [RL_G6K2FRT_8P_5V_GR]  400.3 293.12 0 bottom
UNK2K22  G6K-2F-RF-T-5V-SPECIAL  [RL_G6K2FRT_8P_5V_GR]  373.13 228.6 0 bottom
UNK2K23  G6K-2F-RF-T-5V-SPECIAL  [RL_G6K2FRT_8P_5V_GR]  386.84 228.85 0 bottom
UNK2K24  G6K-2F-RF-T-5V-SPECIAL  [RL_G6K2FRT_8P_5V_GR]  386.84 245.11 0 bottom
UNK2K25  G6K-2F-RF-T-5V-SPECIAL  [RL_G6K2FRT_8P_5V_GR]  400.3 229.11 0 bottom
UNK2K26  G6K-2F-RF-T-5V-SPECIAL  [RL_G6K2FRT_8P_5V_GR]  393.45 213.36 0 bottom
UNK2K27  G6K-2F-RF-T-5V-SPECIAL  [RL_G6K2FRT_8P_5V_GR]  379.98 213.11 0 bottom
UNK2K28  UA2-5NJ-A-V3  [RL_NECUA2_5V_V3]  479.04 237.49 180 bottom
UNK2K29  G6K-2F-RF-T-5V-SPECIAL  [RL_G6K2FRT_8P_5V_GR]  373.13 245.11 0 bottom
UNK2K30  G6K-2F-RF-T-5V-SPECIAL  [RL_G6K2FRT_8P_5V_GR]  414.27 245.11 0 bottom
UNK2K31  EC2-5NJ-A  [RL_NECEC2_10P_5V]  506.73 294.64 90 bottom
UNK2K33  NC/UA2-5NJ-A-V3  [RL_NECUA2_5V_V3]  455.68 237.74 0 bottom
UNK2K34  EC2-5NJ-A  [RL_NECEC2_10P_5V]  457.2 294.64 90 bottom
UNK2K36  EC2-5NJ-A  [RL_NECEC2_10P_5V]  490.22 294.64 90 bottom
UNK2K37  EC2-5NJ-A  [RL_NECEC2_10P_5V]  457.2 278.13 90 bottom
UNK2K39  EC2-5NJ-A  [RL_NECEC2_10P_5V]  490.22 278.13 90 bottom
UNK2K40  EC2-5NJ-A  [RL_NECEC2_10P_5V]  473.71 294.64 90 bottom
UNK2K42  EC2-5NJ-A  [RL_NECEC2_10P_5V]  473.71 278.13 90 bottom
UNK2K43  G6K-2F-RF-T-5V-SPECIAL  [RL_G6K2FRT_8P_5V_GR]  386.84 261.11 0 bottom
UNK2R1  NC/1M-1-S4  [R0402]  301.23 227.84 180 bottom
UNK2R2  NC/1M-1-S4  [R0402]  298.95 227.84 0 bottom
UNK2R3  NC/100K-1-S4  [R0402]  289.81 130.81 180 bottom
UNK2R4  NC/100K-1-S4  [R0402]  287.27 130.81 180 bottom
UNK2R5  0-5-S4  [R0402]  302.38 272.16 270 bottom
UNK2R6  1M-1-S4  [R0402]  302.38 274.32 270 bottom
UNK2R7  49.9-1-S4  [R0402]  415.95 299.91 180 bottom
UNK2R8  49.9-1-S4  [R0402]  418.1 299.91 180 bottom
UNK2R9  49.9-1-S4  [R0402]  415.95 286.32 180 bottom
UNK2R10  49.9-1-S4  [R0402]  418.1 286.32 180 bottom
UNK2R11  49.9-1-S4  [R0402]  415.95 284.16 180 bottom
UNK2R12  49.9-1-S4  [R0402]  418.1 284.16 180 bottom
UNK2R13  49.9-1-S4  [R0402]  415.95 270.57 180 bottom
UNK2R14  49.9-1-S4  [R0402]  418.1 270.57 180 bottom
UNK2R15  49.9-1-S4  [R0402]  401.98 251.9 180 bottom
UNK2R16  49.9-1-S4  [R0402]  404.13 251.9 180 bottom
UNK2R17  49.9-1-S4  [R0402]  401.98 238.32 180 bottom
UNK2R18  49.9-1-S4  [R0402]  404.13 238.32 180 bottom
UNK2R19  49.9-1-S4  [R0402]  375.06 283.91 180 bottom
UNK2R20  49.9-1-S4  [R0402]  377.2 283.91 180 bottom
UNK2R21  49.9-1-S4  [R0402]  375.06 270.32 180 bottom
UNK2R22  49.9-1-S4  [R0402]  377.2 270.32 180 bottom
UNK2R23  49.9-1-S4  [R0402]  401.98 268.16 180 bottom
UNK2R24  49.9-1-S4  [R0402]  404.13 268.16 180 bottom
UNK2R25  49.9-1-S4  [R0402]  401.98 254.57 180 bottom
UNK2R26  49.9-1-S4  [R0402]  404.13 254.57 180 bottom
UNK2R27  49.9-1-S4  [R0402]  401.98 283.91 180 bottom
UNK2R28  49.9-1-S4  [R0402]  404.13 283.91 180 bottom
UNK2R29  49.9-1-S4  [R0402]  401.98 270.32 180 bottom
UNK2R30  49.9-1-S4  [R0402]  404.13 270.32 180 bottom
UNK2R31  49.9-1-S4  [R0402]  388.52 283.91 180 bottom
UNK2R32  49.9-1-S4  [R0402]  390.66 283.91 180 bottom
UNK2R33  49.9-1-S4  [R0402]  388.52 270.32 180 bottom
UNK2R34  49.9-1-S4  [R0402]  390.66 270.32 180 bottom
UNK2R37  49.9-1-S4  [R0402]  388.52 286.32 180 bottom
UNK2R38  49.9-1-S4  [R0402]  390.66 286.32 180 bottom
UNK2R39  49.9-1-S4  [R0402]  415.7 268.16 180 bottom
UNK2R40  49.9-1-S4  [R0402]  417.84 268.16 180 bottom
UNK2R41  49.9-1-S4  [R0402]  415.7 254.57 180 bottom
UNK2R42  49.9-1-S4  [R0402]  417.84 254.57 180 bottom
UNK2R43  49.9-1-S4  [R0402]  374.8 238.32 180 bottom
UNK2R44  49.9-1-S4  [R0402]  376.95 238.32 180 bottom
UNK2R45  49.9-1-S4  [R0402]  374.8 221.81 180 bottom
UNK2R46  49.9-1-S4  [R0402]  376.95 221.81 180 bottom
UNK2R47  49.9-1-S4  [R0402]  388.52 235.65 180 bottom
UNK2R48  49.9-1-S4  [R0402]  390.66 235.65 180 bottom
UNK2R49  49.9-1-S4  [R0402]  388.52 222.06 180 bottom
UNK2R50  49.9-1-S4  [R0402]  390.66 222.06 180 bottom
UNK2R51  49.9-1-S4  [R0402]  388.52 251.9 180 bottom
UNK2R52  49.9-1-S4  [R0402]  390.66 251.9 180 bottom
UNK2R53  49.9-1-S4  [R0402]  388.52 238.32 180 bottom
UNK2R54  49.9-1-S4  [R0402]  390.66 238.32 180 bottom
UNK2R55  49.9-1-S4  [R0402]  401.98 235.9 180 bottom
UNK2R56  49.9-1-S4  [R0402]  404.13 235.9 180 bottom
UNK2R57  49.9-1-S4  [R0402]  401.98 222.31 180 bottom
UNK2R58  49.9-1-S4  [R0402]  404.13 222.31 180 bottom
UNK2R59  49.9-1-S4  [R0402]  395.12 220.15 180 bottom
UNK2R60  49.9-1-S4  [R0402]  397.27 220.15 180 bottom
UNK2R61  49.9-1-S4  [R0402]  395.12 206.57 180 bottom
UNK2R62  49.9-1-S4  [R0402]  397.27 206.57 180 bottom
UNK2R63  49.9-1-S4  [R0402]  415.95 251.9 180 bottom
UNK2R64  49.9-1-S4  [R0402]  418.1 251.9 180 bottom
UNK2R65  49.9-1-S4  [R0402]  381.66 206.31 180 bottom
UNK2R66  49.9-1-S4  [R0402]  383.81 206.31 180 bottom
UNK2R67  49.9-1-S4  [R0402]  374.8 267.91 180 bottom
UNK2R68  49.9-1-S4  [R0402]  376.95 267.91 180 bottom
UNK2R69  49.9-1-S4  [R0402]  374.8 254.32 180 bottom
UNK2R70  49.9-1-S4  [R0402]  376.95 254.32 180 bottom
UNK2R71  49.9-1-S4  [R0402]  375.06 299.91 180 bottom
UNK2R72  49.9-1-S4  [R0402]  377.2 299.91 180 bottom
UNK2R73  49.9-1-S4  [R0402]  375.06 286.32 180 bottom
UNK2R74  49.9-1-S4  [R0402]  377.2 286.32 180 bottom
UNK2R75  49.9-1-S4  [R0402]  401.98 299.91 180 bottom
UNK2R76  49.9-1-S4  [R0402]  404.13 299.91 180 bottom
UNK2R77  49.9-1-S4  [R0402]  401.98 286.32 180 bottom
UNK2R78  49.9-1-S4  [R0402]  404.13 286.32 180 bottom
UNK2R79  49.9-1-S4  [R0402]  374.8 251.9 180 bottom
UNK2R80  49.9-1-S4  [R0402]  376.95 251.9 180 bottom
UNK2R82  4.7K-1-S4-WA  [R0402]  456.75 233.88 0 bottom
UNK2R83  4.7K-1-S4-WA  [R0402]  482.6 241.3 0 bottom
UNK2R84  4.7K-1-S4-WA  [R0402]  482.6 233.68 0 bottom
UNK2R85  100K-1-S4  [R0402]  465.07 235.71 0 bottom
UNK2R86  4.7K-1-S4-WA  [R0402]  486.3 226.62 0 bottom
UNK2R87  4.7K-1-S4-WA  [R0402]  475.49 230.78 0 bottom
UNK2R88  4.7K-1-S4-WA  [R0402]  478.03 230.78 0 bottom
UNK2R89  4.7K-1-S4-WA  [R0402]  490.6 226.67 180 bottom
UNK2R90  4.7K-1-S4-WA  [R0402]  478.03 218.59 0 bottom
UNK2R91  4.7K-1-S4-WA  [R0402]  480.57 218.59 0 bottom
UNK2R92  4.7K-1-S4-WA  [R0402]  483.11 218.59 0 bottom
UNK2R93  4.7K-1-S4-WA  [R0402]  486.3 212.91 0 bottom
UNK2R94  4.7K-1-S4-WA  [R0402]  475.37 217.23 180 bottom
UNK2R95  4.7K-1-S4-WA  [R0402]  477.93 217.17 0 bottom
UNK2R96  4.7K-1-S4-WA  [R0402]  490.36 212.91 180 bottom
UNK2R97  4.7K-1-S4-WA  [R0402]  477.93 204.98 0 bottom
UNK2R98  4.7K-1-S4-WA  [R0402]  480.47 204.98 0 bottom
UNK2R99  4.7K-1-S4-WA  [R0402]  483.01 204.98 0 bottom
UNK2R100  49.9-1-S4  [R0402]  415.95 238.32 180 bottom
UNK2R101  49.9-1-S4  [R0402]  418.1 238.32 180 bottom
UNK2R102  49.9-1-S4  [R0402]  374.8 235.39 180 bottom
UNK2R103  49.9-1-S4  [R0402]  376.95 235.39 180 bottom
UNK2R104  49.9-1-S4  [R0402]  381.66 219.9 180 bottom
UNK2R105  49.9-1-S4  [R0402]  383.81 219.9 180 bottom
UNK2R117  1K-1-S4  [R0402]  452.18 233.88 0 bottom
UNK2R118  NC/0-5-S4  [R0402]  310.41 245.39 180 bottom
UNK2R119  4.7K-1-S4-WA  [R0402]  452.12 224.79 180 bottom
UNK2R120  4.7K-1-S4-WA  [R0402]  452.12 232.41 180 bottom
UNK2R125  0-5-S4  [R0402]  456.44 209.55 0 bottom
UNK2R126  0-5-S4  [R0402]  452.37 209.55 0 bottom
UNK2R127  0-5-S4  [R0402]  456.69 217.17 0 bottom
UNK2R128  0-5-S4  [R0402]  452.12 217.17 0 bottom
UNK2R129  0-5-S4  [R0402]  301.23 229.11 180 bottom
UNK2R130  0-5-S4  [R0402]  298.95 229.11 0 bottom
UNK2R131  50-0.1-S4-HF-VI  [R0402]  303.77 243.33 90 bottom
UNK2R132  50-0.1-S4-HF-VI  [R0402]  296.15 243.33 90 bottom
UNK2R133  0-5-S4  [R0402]  302.38 276.48 90 bottom
UNK2SH1  SHORT  [DEFAULT_SHORT_SMALL]  462.05 291.99 0 top
UNK2SH2  SHORT  [DEFAULT_SHORT_SMALL]  464 291.99 0 top
UNK2SH3  SHORT  [DEFAULT_SHORT_SMALL]  452.21 291.99 0 top
UNK2SH4  SHORT  [DEFAULT_SHORT_SMALL]  450.26 292.12 180 top
UNK2SH5  SHORT  [DEFAULT_SHORT_SMALL]  485.23 291.99 0 top
UNK2SH6  SHORT  [DEFAULT_SHORT_SMALL]  483.28 292.12 180 top
UNK2SH7  SHORT  [DEFAULT_SHORT_SMALL]  462.05 275.48 0 top
UNK2SH8  SHORT  [DEFAULT_SHORT_SMALL]  450.26 275.61 180 top
UNK2SH9  SHORT  [DEFAULT_SHORT_SMALL]  464 275.48 0 top
UNK2SH10  SHORT  [DEFAULT_SHORT_SMALL]  452.21 275.48 0 top
UNK2SH11  SHORT  [DEFAULT_SHORT_SMALL]  483.28 275.61 180 top
UNK2SH12  SHORT  [DEFAULT_SHORT_SMALL]  495.07 275.48 0 top
UNK2SH13  SHORT  [DEFAULT_SHORT_SMALL]  480.51 291.99 0 top
UNK2SH14  SHORT  [DEFAULT_SHORT_SMALL]  478.56 291.99 0 top
UNK2SH15  SHORT  [DEFAULT_SHORT_SMALL]  466.77 292.12 180 top
UNK2SH16  SHORT  [DEFAULT_SHORT_SMALL]  468.72 291.99 0 top
UNK2SH17  SHORT  [DEFAULT_SHORT_SMALL]  466.77 275.61 180 top
UNK2SH18  SHORT  [DEFAULT_SHORT_SMALL]  478.56 275.48 0 top
UNK2SH19  SHORT  [DEFAULT_SHORT_SMALL]  90.17 246.75 0 top
UNK2SH20  SHORT  [DEFAULT_SHORT_SMALL]  92.37 246.75 0 top
UNK2SH21  SHORT  [DEFAULT_SHORT_SMALL]  85.31 246.8 0 top
UNK2SH22  SHORT  [DEFAULT_SHORT_SMALL]  87.51 246.8 0 top
UNK2SH23  SHORT  [DEFAULT_SHORT_SMALL]  511.58 291.99 0 top
UNK2SH24  SHORT  [DEFAULT_SHORT_SMALL]  513.76 291.86 180 top
UNK2SH25  SHORT  [DEFAULT_SHORT_SMALL]  485.23 275.48 0 top
UNK2SH26  SHORT  [DEFAULT_SHORT_SMALL]  497.02 275.48 0 top
UNK2SH27  SHORT  [DEFAULT_SHORT_SMALL]  468.72 275.48 0 top
UNK2SH28  SHORT  [DEFAULT_SHORT_SMALL]  480.51 275.48 0 top
UNK2TP_AUXVCC  TP01  [TP_040_T]  92.04 247.9 180 top
UNK2TP_AVDD11_RX  TP01  [TP_040_T]  452.33 276.86 180 top
UNK2TP_AVDD11_XTAL  TP01  [TP_040_T]  511.6 293.37 0 top
UNK2TP_AVDD18_RX  TP01  [TP_040_T]  462.07 276.86 0 top
UNK2TP_PLL_M_VDD33  TP01  [TP_040_T]  478.58 293.37 0 top
UNK2TP_PLL_TX_VDD33  TP01  [TP_040_T]  468.84 293.37 180 top
UNK2TP_VCC3V3  TP01  [TP_040_T]  87.17 247.96 180 top
UNK2TP_VDD_IO_33  TP01  [TP_040_T]  452.33 293.37 180 top
UNK2TP_VDD_TXREG_33_B  TP01  [TP_040_T]  478.58 276.86 0 top
UNK2TP_VDD_TXREG_33_T  TP01  [TP_040_T]  468.84 276.86 180 top
UNK2TP_VDDA_33_LV  TP01  [TP_040_T]  462.07 293.37 0 top
UNK2TP_VDDC_11  TP01  [TP_040_T]  485.35 293.37 180 top
UNK2TP_VDDTXPST_11_B  TP01  [TP_040_T]  495.09 276.86 0 top
UNK2TP_VDDTXPST_11_T  TP01  [TP_040_T]  485.35 276.86 180 top
UNK2TP_XTAL_IN  TP01  [TP_040_T]  306.85 271.67 0 top
UNK2TP_XTAL_OUT  TP01  [TP_040_T]  306.85 276.97 0 top
UNK2U1  SOLDER-DIP8-SOCKET  [DIP8_300X100_RLPIN]  474.97 228.55 270 bottom
UNK2U2  SOLDER-DIP8-SOCKET  [DIP8_300X100_RLPIN]  474.87 214.94 270 bottom
UNK2UF1  MX25L4006EM2I-12G-SOP8  [SOCKET_CODE]  360.09 283.74 180 top
UNK2UF2  MX25L4006EM2I-12G-SOP8  [SOCKET_CODE]  474.97 228.55 90 top
UNK2Y1  XTAL27M-S2520-ABRACON-10P  [XTAL_2X2P5MM_4P]  298.76 274.89 270 bottom
UNK2Y2  NC/XTAL27M-S3225-TXC-10P  [XTAL_3P2X2P5MM_4P_TXC_0201]  298.76 274.89 270 bottom
UNK3C3  0.1U-16-X-S4-MU  [C0402]  192.28 132.33 180 bottom
UNK3C4  0.1U-16-X-S4-MU  [C0402]  189.74 132.33 180 bottom
UNK3C5  22P-50-N-S4-AVX  [C0402]  221.21 217.48 90 bottom
UNK3C6  22P-50-N-S4-AVX  [C0402]  221.21 211.16 270 bottom
UNK3C7  0.1U-16-X-S4-MU  [C0402]  111 186.44 0 bottom
UNK3C8  0.1U-16-X-S4-MU  [C0402]  104.39 171.81 180 bottom
UNK3C9  0.1U-16-X-S4-MU  [C0402]  104.49 185.42 180 bottom
UNK3CA1  NC/10U-10-X6S-S6-MU  [C0603]  112.39 290.83 0 bottom
UNK3CA2  NC/47U-10-X5R-S8-TDK  [C0805]  112.5 292.74 0 bottom
UNK3CA3  NC/10U-10-X6S-S6-MU  [C0603]  100.96 290.83 180 bottom
UNK3CA4  NC/47U-10-X5R-S8-TDK  [C0805]  100.86 292.74 180 bottom
UNK3CA5  NC/10U-10-X6S-S6-MU  [C0603]  100.96 274.32 180 bottom
UNK3CA6  NC/47U-10-X5R-S8-TDK  [C0805]  100.86 276.23 180 bottom
UNK3CA7  NC/10U-10-X6S-S6-MU  [C0603]  128.9 274.32 0 bottom
UNK3CA8  NC/47U-10-X5R-S8-TDK  [C0805]  129.01 276.23 0 bottom
UNK3CA9  NC/10U-10-X6S-S6-MU  [C0603]  117.47 274.32 180 bottom
UNK3CA10  NC/47U-10-X5R-S8-TDK  [C0805]  117.37 276.23 180 bottom
UNK3CA11  NC/10U-10-X6S-S6-MU  [C0603]  76.83 290.83 0 bottom
UNK3CA12  NC/47U-10-X5R-S8-TDK  [C0805]  76.94 292.74 0 bottom
UNK3CA13  NC/47U-10-X5R-S8-TDK  [C0805]  94.72 292.74 0 bottom
UNK3CA14  NC/10U-10-X6S-S6-MU  [C0603]  94.61 290.83 0 bottom
UNK3CA15  NC/47U-10-X5R-S8-TDK  [C0805]  83.08 292.74 180 bottom
UNK3CA16  NC/10U-10-X6S-S6-MU  [C0603]  83.18 290.83 180 bottom
UNK3CA17  NC/47U-10-X5R-S8-TDK  [C0805]  76.94 276.23 0 bottom
UNK3CA18  NC/10U-10-X6S-S6-MU  [C0603]  76.83 274.32 0 bottom
UNK3CA19  NC/47U-10-X5R-S8-TDK  [C0805]  111.1 249.13 180 bottom
UNK3CA20  NC/10U-10-X6S-S6-MU  [C0603]  111.2 247.23 180 bottom
UNK3CA21  10U-10-X6S-S6-MU  [C0603]  112.39 288.29 0 bottom
UNK3CA22  10U-10-X6S-S6-MU  [C0603]  100.96 288.29 180 bottom
UNK3CA23  10U-10-X6S-S6-MU  [C0603]  100.96 271.78 180 bottom
UNK3CA24  10U-10-X6S-S6-MU  [C0603]  128.9 271.78 0 bottom
UNK3CA25  10U-10-X6S-S6-MU  [C0603]  117.47 271.78 180 bottom
UNK3CA26  10U-10-X6S-S6-MU  [C0603]  76.83 288.29 0 bottom
UNK3CA27  10U-10-X6S-S6-MU  [C0603]  94.61 288.29 0 bottom
UNK3CA28  10U-10-X6S-S6-MU  [C0603]  83.18 288.29 180 bottom
UNK3CA29  10U-10-X6S-S6-MU  [C0603]  76.83 271.78 0 bottom
UNK3CA30  NC/47U-10-X5R-S8-TDK  [C0805]  106.23 249.19 180 bottom
UNK3CA31  10U-10-X6S-S6-MU  [C0603]  106.33 247.28 180 bottom
